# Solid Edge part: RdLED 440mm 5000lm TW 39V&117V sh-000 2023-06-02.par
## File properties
Author: robert.pupel
Template: iso metric part.par
Last saved by: robert.pupel
Revision: 1
Application: Solid Edge
Gęstość: 0.000 kg/m^3
Dokładność: 0.990
Username: robert.pupel
Revision: 02
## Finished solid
Body 1: solid body, 407 faces, 1027 edges, 637 vertices.
  Faces by surface: plane 163, cylinder 115, torus 52, cone 44, spline 23, sphere 10
  Edges by curve: line 496, curve on surface 311, circle 123, ellipse 66, spline 31
Body 2: solid body, 407 faces, 1027 edges, 637 vertices.
  Faces by surface: plane 163, cylinder 115, torus 52, cone 44, spline 23, sphere 10
  Edges by curve: line 496, curve on surface 311, circle 123, ellipse 66, spline 31
Body 3: solid body, 17 faces, 42 edges, 28 vertices.
  Faces by surface: plane 17
  Edges by curve: line 42
Body 4: solid body, 17 faces, 42 edges, 28 vertices.
  Faces by surface: plane 17
  Edges by curve: line 42
Body 5: solid body, 17 faces, 42 edges, 28 vertices.
  Faces by surface: plane 17
  Edges by curve: line 42
Body 6: solid body, 17 faces, 42 edges, 28 vertices.
  Faces by surface: plane 17
  Edges by curve: line 42
Body 7: solid body, 17 faces, 42 edges, 28 vertices.
  Faces by surface: plane 17
  Edges by curve: line 42
Body 8: solid body, 17 faces, 42 edges, 28 vertices.
  Faces by surface: plane 17
  Edges by curve: line 42
Body 9: solid body, 17 faces, 42 edges, 28 vertices.
  Faces by surface: plane 17
  Edges by curve: line 42
Body 10: solid body, 17 faces, 42 edges, 28 vertices.
  Faces by surface: plane 17
  Edges by curve: line 42
Body 11: solid body, 17 faces, 42 edges, 28 vertices.
  Faces by surface: plane 17
  Edges by curve: line 42
Body 12: solid body, 17 faces, 42 edges, 28 vertices.
  Faces by surface: plane 17
  Edges by curve: line 42
Body 13: solid body, 17 faces, 42 edges, 28 vertices.
  Faces by surface: plane 17
  Edges by curve: line 42
Body 14: solid body, 17 faces, 42 edges, 28 vertices.
  Faces by surface: plane 17
  Edges by curve: line 42
Body 15: solid body, 17 faces, 42 edges, 28 vertices.
  Faces by surface: plane 17
  Edges by curve: line 42
Body 16: solid body, 17 faces, 42 edges, 28 vertices.
  Faces by surface: plane 17
  Edges by curve: line 42
Body 17: solid body, 17 faces, 42 edges, 28 vertices.
  Faces by surface: plane 17
  Edges by curve: line 42
Body 18: solid body, 17 faces, 42 edges, 28 vertices.
  Faces by surface: plane 17
  Edges by curve: line 42
Body 19: solid body, 17 faces, 42 edges, 28 vertices.
  Faces by surface: plane 17
  Edges by curve: line 42
Body 20: solid body, 17 faces, 42 edges, 28 vertices.
  Faces by surface: plane 17
  Edges by curve: line 42
Body 21: solid body, 17 faces, 42 edges, 28 vertices.
  Faces by surface: plane 17
  Edges by curve: line 42
Body 22: solid body, 17 faces, 42 edges, 28 vertices.
  Faces by surface: plane 17
  Edges by curve: line 42
Body 23: solid body, 17 faces, 42 edges, 28 vertices.
  Faces by surface: plane 17
  Edges by curve: line 42
Body 24: solid body, 17 faces, 42 edges, 28 vertices.
  Faces by surface: plane 17
  Edges by curve: line 42
Body 25: solid body, 17 faces, 42 edges, 28 vertices.
  Faces by surface: plane 17
  Edges by curve: line 42
Body 26: solid body, 17 faces, 42 edges, 28 vertices.
  Faces by surface: plane 17
  Edges by curve: line 42
Body 27: solid body, 17 faces, 42 edges, 28 vertices.
  Faces by surface: plane 17
  Edges by curve: line 42
Body 28: solid body, 17 faces, 42 edges, 28 vertices.
  Faces by surface: plane 17
  Edges by curve: line 42
Body 29: solid body, 17 faces, 42 edges, 28 vertices.
  Faces by surface: plane 17
  Edges by curve: line 42
Body 30: solid body, 17 faces, 42 edges, 28 vertices.
  Faces by surface: plane 17
  Edges by curve: line 42
Body 31: solid body, 17 faces, 42 edges, 28 vertices.
  Faces by surface: plane 17
  Edges by curve: line 42
Body 32: solid body, 17 faces, 42 edges, 28 vertices.
  Faces by surface: plane 17
  Edges by curve: line 42
Body 33: solid body, 17 faces, 42 edges, 28 vertices.
  Faces by surface: plane 17
  Edges by curve: line 42
Body 34: solid body, 17 faces, 42 edges, 28 vertices.
  Faces by surface: plane 17
  Edges by curve: line 42
Body 35: solid body, 17 faces, 42 edges, 28 vertices.
  Faces by surface: plane 17
  Edges by curve: line 42
Body 36: solid body, 17 faces, 42 edges, 28 vertices.
  Faces by surface: plane 17
  Edges by curve: line 42
Body 37: solid body, 17 faces, 42 edges, 28 vertices.
  Faces by surface: plane 17
  Edges by curve: line 42
Body 38: solid body, 17 faces, 42 edges, 28 vertices.
  Faces by surface: plane 17
  Edges by curve: line 42
Body 39: solid body, 17 faces, 42 edges, 28 vertices.
  Faces by surface: plane 17
  Edges by curve: line 42
Body 40: solid body, 17 faces, 42 edges, 28 vertices.
  Faces by surface: plane 17
  Edges by curve: line 42
Body 41: solid body, 17 faces, 42 edges, 28 vertices.
  Faces by surface: plane 17
  Edges by curve: line 42
Body 42: solid body, 17 faces, 42 edges, 28 vertices.
  Faces by surface: plane 17
  Edges by curve: line 42
Body 43: solid body, 17 faces, 42 edges, 28 vertices.
  Faces by surface: plane 17
  Edges by curve: line 42
Body 44: solid body, 17 faces, 42 edges, 28 vertices.
  Faces by surface: plane 17
  Edges by curve: line 42
Body 45: solid body, 17 faces, 42 edges, 28 vertices.
  Faces by surface: plane 17
  Edges by curve: line 42
Body 46: solid body, 17 faces, 42 edges, 28 vertices.
  Faces by surface: plane 17
  Edges by curve: line 42
Body 47: solid body, 17 faces, 42 edges, 28 vertices.
  Faces by surface: plane 17
  Edges by curve: line 42
Body 48: solid body, 17 faces, 42 edges, 28 vertices.
  Faces by surface: plane 17
  Edges by curve: line 42
Body 49: solid body, 17 faces, 42 edges, 28 vertices.
  Faces by surface: plane 17
  Edges by curve: line 42
Body 50: solid body, 17 faces, 42 edges, 28 vertices.
  Faces by surface: plane 17
  Edges by curve: line 42
Body 51: solid body, 17 faces, 42 edges, 28 vertices.
  Faces by surface: plane 17
  Edges by curve: line 42
Body 52: solid body, 17 faces, 42 edges, 28 vertices.
  Faces by surface: plane 17
  Edges by curve: line 42
Body 53: solid body, 17 faces, 42 edges, 28 vertices.
  Faces by surface: plane 17
  Edges by curve: line 42
Body 54: solid body, 17 faces, 42 edges, 28 vertices.
  Faces by surface: plane 17
  Edges by curve: line 42
Body 55: solid body, 17 faces, 42 edges, 28 vertices.
  Faces by surface: plane 17
  Edges by curve: line 42
Body 56: solid body, 17 faces, 42 edges, 28 vertices.
  Faces by surface: plane 17
  Edges by curve: line 42
Body 57: solid body, 17 faces, 42 edges, 28 vertices.
  Faces by surface: plane 17
  Edges by curve: line 42
Body 58: solid body, 17 faces, 42 edges, 28 vertices.
  Faces by surface: plane 17
  Edges by curve: line 42
Body 59: solid body, 17 faces, 42 edges, 28 vertices.
  Faces by surface: plane 17
  Edges by curve: line 42
Body 60: solid body, 17 faces, 42 edges, 28 vertices.
  Faces by surface: plane 17
  Edges by curve: line 42
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Bounding box of the edges (mm; curved faces can reach further): 428.000 x 4.450 x 428.000, from (-214, -3.45, -214) to (214, 1, 214).
Cylindrical faces by radius (mm): R0.199 x2, R0.2 x78, R0.2002 x4, R0.2169 x6, R0.25 x24, R0.3 x4, R0.3373 x6, R0.4 x16, R0.4006 x4, R0.4008 x4, R0.525 x4, R0.6 x24, R1 x14, R1.0894 x4, R1.0991 x8, R1.1 x28, R2.25 x12, R5 x1, R219.9999 x4
Conical faces (half-angle, radius in mm at the cone's reference point): 0.3913 deg R1.0968 x4, 0.447 deg R1.0952 x4, 0.464 deg R1.0955 x4, 0.5 deg R0.5056 x8, 0.5 deg R1.0082 x8, 1 deg R0.5511 x4, 10 deg R0.2132 x4, 10 deg R0.4132 x4, 15.6748 deg R1.1041 x2, 15.6751 deg R1.1041 x2, 15.7937 deg R1.1267 x2, 15.7938 deg R1.1267 x2, 18.4844 deg R1.0657 x8, 18.9316 deg R0.5099 x4, 19.4337 deg R0.5111 x4, 27.363 deg R0.6214 x4, 40.1968 deg R0.519 x2, 40.228 deg R0.5176 x2, 42.9179 deg R0.4919 x2, 42.9331 deg R0.4916 x2, 45 deg R0.575 x4, 45 deg R0.625 x8
Toroidal faces (ring radius, tube radius in mm): R0.0958 r0.3997 x8, R0.1 r0.2 x2, R0.1075 r0.4 x4, R0.1101 r0.4001 x4, R0.1216 r0.4 x4, R0.1234 r0.4 x4, R0.1634 r0.2287 x2, R0.1641 r0.2287 x2, R0.3286 r0.2001 x2, R0.3702 r0.4 x4, R0.3818 r0.2 x4, R0.4163 r0.3984 x4, R0.4824 r0.2001 x2, R0.4952 r0.2 x2, R0.6008 r0.3968 x4, R0.6009 r0.3969 x4, R0.6227 r0.2 x2, R0.6235 r0.2 x2, R0.8 r0.2 x8, R0.8522 r0.3 x4, R0.9002 r0.2 x2, R0.9018 r0.2 x2, R0.9181 r0.2227 x4, R0.9197 r0.223 x2, R0.9199 r0.223 x2, R0.9663 r0.2263 x2, R0.9665 r0.2263 x2, R1.3 r0.2 x4, R1.327 r1.1 x4, R1.3271 r1.1 x4, R1.8741 r0.2175 x2, R1.8987 r0.2 x2
Spherical faces by radius (mm): R0.2 x16, R0.6 x4
Planar faces by outward normal: +x 63, +y 335, +z 71, -x 81, -y 975, -z 71, oblique 4104
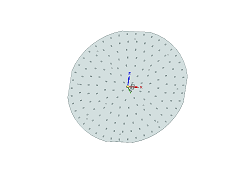
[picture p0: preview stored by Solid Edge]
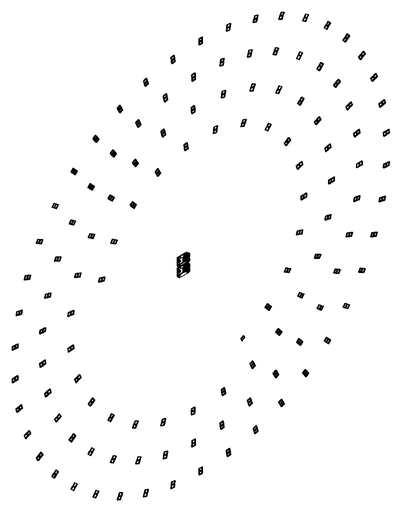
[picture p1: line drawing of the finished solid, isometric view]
